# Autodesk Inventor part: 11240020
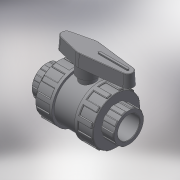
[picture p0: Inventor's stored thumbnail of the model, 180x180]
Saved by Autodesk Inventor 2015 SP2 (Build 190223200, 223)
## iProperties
Created: 2017-11
Part Number: 11240020
Material: Generic
Description: PLASSON BI STOP VALVE CEM PVC 20
Document SubType Name: Modeling
Designer: KIM
Density: 1 g/cm^3
Appearance: Default
Author: KIM
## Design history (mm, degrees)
derived "112400 - 112700.ipt"
feature "Solid1::112400 - 112700.ipt"
tag "TaggingFeature1"
body "Solid1"
other parameters: "d0" = 75, "d2" = 45, "d3" = 16, "d4" = 16, "d5" = 11.2, "d7" = 28, "d8" = 40.5, "d13" = 0.6, "d23" = 16, "d24" = 43.2, "d25" = 0.4, "d26" = 0.6, "d27" = 6.75, "d28" = 3.375, "d29" = 12, "d30" = 0, "d35" = 0.6, "d39" = 22.5, "d45" = 360 deg, "d47" = 0.4, "d50" = 24.75, "d51" = 13.5, "d53" = 0, "d55" = 4, "d56" = 2, "d57" = 11.2, "d58" = 0, "d59" = 0.6, "d61" = 360 deg, "d63" = 18, "d64" = 45, "d66" = 65, "d68" = 9, "d69" = 19.5, "d70" = 11.25, "d71" = 3 deg, "d73" = 0.9, "d74" = 26, "d75" = 1.35, "d76" = 0, "d77" = 0.4, "l_" = 16, "H_" = 75, "K_" = 45, "F_" = 45, "J_" = 65, "d67" = 18, "d72" = 4.5
